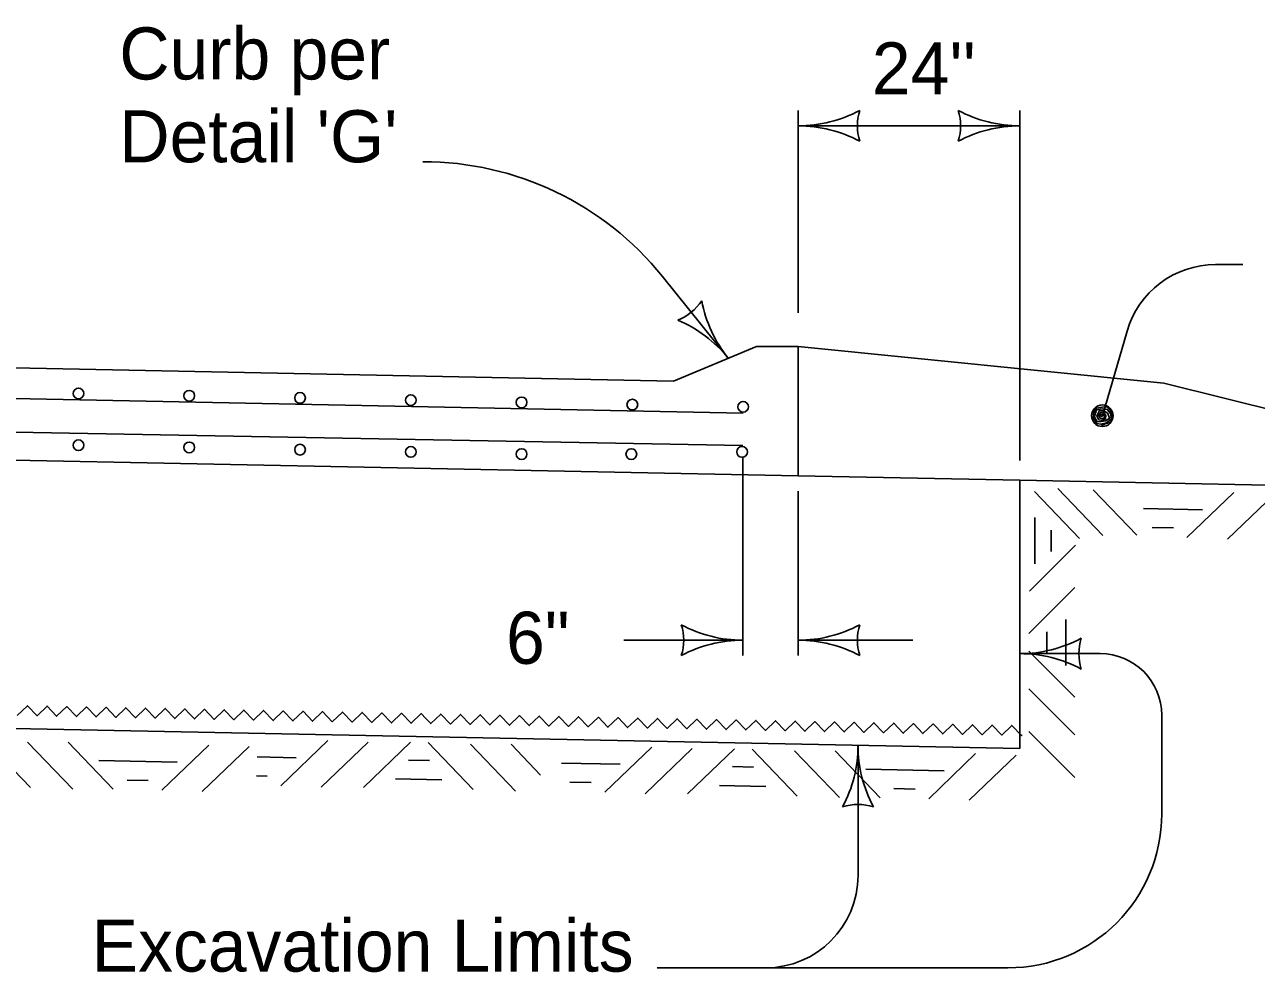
# Model space of a CAD drawing. Extents: x -2135039 to -2124495, y -2139046 to -2132546.
# Drawn here: x -2126978.8 to -2126600.4, y -2137518.2 to -2137227.1 of the extents above; entities that cross this region are included whole.
import ezdxf

# ---------------------------------------------------------------- set-up
doc = ezdxf.new("R2010")
doc.units = 0
doc.layers.add('BridgeSuperStructureExisting', color=7, linetype='Continuous')
doc.layers.add('dsnStdLabel', color=7, linetype='Continuous')

msp = doc.modelspace()

# ---------------------------------------------------------------- linework, layer by layer
at = {"layer": 'BridgeSuperStructureExisting'}
for p, q in [((-2126741.2, -2137315.6), (-2126741.2, -2137253.45)), ((-2126673.14, -2137360.94), (-2126673.14, -2137253.45)), ((-2126673.14, -2137258.17), (-2126741.2, -2137258.17)), ((-2126604.57, -2137300.82), (-2126612.95, -2137300.82)), ((-2126782.93, -2137304.43), (-2126762.67, -2137329.6)), ((-2126779.48, -2137336.57), (-2127489.73, -2137322.31)), ((-2127489.73, -2137322.31), (-2126779.48, -2137336.57)), ((-2126640.18, -2137321.24), (-2126647.76, -2137347.24)), ((-2126753.96, -2137325.99), (-2126779.48, -2137336.57)), ((-2126779.48, -2137336.57), (-2126753.96, -2137325.99)), ((-2126741.2, -2137325.99), (-2126753.96, -2137325.99)), ((-2126741.2, -2137325.99), (-2126753.96, -2137325.99)), ((-2126741.2, -2137365.7), (-2126741.2, -2137325.99)), ((-2126741.2, -2137365.7), (-2126741.2, -2137325.99)), ((-2126741.2, -2137325.99), (-2126628.92, -2137337.22)), ((-2127489.77, -2137331.8), (-2126758.11, -2137346.48)), ((-2126628.92, -2137337.22), (-2126380.66, -2137399.31)), ((-2126928.2, -2137342.96), (-2126928.2, -2137342.96)), ((-2126894.17, -2137343.64), (-2126894.17, -2137343.64)), ((-2126826.1, -2137345), (-2126826.1, -2137345)), ((-2127490.3, -2137350.67), (-2126741.2, -2137365.7)), ((-2127489.16, -2137350.69), (-2126741.2, -2137365.7)), ((-2126962.47, -2137354.64), (-2126962.47, -2137354.64)), ((-2126928.44, -2137355.33), (-2126928.44, -2137355.33)), ((-2126894.4, -2137356.01), (-2126894.4, -2137356.01)), ((-2126860.37, -2137356.69), (-2126860.37, -2137356.69)), ((-2126826.34, -2137357.38), (-2126826.34, -2137357.38)), ((-2126758.21, -2137360.18), (-2126758.21, -2137420.92)), ((-2126741.2, -2137365.7), (-2126673.14, -2137367.07)), ((-2126673.14, -2137449.49), (-2126673.14, -2137367.07)), ((-2126673.14, -2137367.07), (-2126495.29, -2137370.64)), ((-2126741.2, -2137370.43), (-2126741.2, -2137420.92)), ((-2126668.64, -2137370.55), (-2126654.79, -2137384.97)), ((-2126661.42, -2137369.62), (-2126647.57, -2137384.04)), ((-2126650.57, -2137369.95), (-2126637.18, -2137383.88)), ((-2126607.35, -2137370.82), (-2126621.77, -2137384.67)), ((-2126594.91, -2137371.29), (-2126609.33, -2137385.15)), ((-2126670.11, -2137401.17), (-2126655.96, -2137387.03)), ((-2126670.33, -2137414.18), (-2126656.19, -2137400.04)), ((-2126758.21, -2137416.2), (-2126794.75, -2137416.2)), ((-2126705.98, -2137416.2), (-2126741.2, -2137416.2)), ((-2126648.42, -2137420.32), (-2126673.14, -2137420.32)), ((-2126670.33, -2137419.59), (-2126656.19, -2137433.73)), ((-2126670.33, -2137431.17), (-2126656.19, -2137445.31)), ((-2127489.73, -2137433.1), (-2126673.14, -2137449.49)), ((-2126629.51, -2137439.23), (-2126629.51, -2137469.59)), ((-2126670.33, -2137444.23), (-2126656.19, -2137458.37)), ((-2126990.95, -2137447.02), (-2126977.09, -2137461.44)), ((-2126977.94, -2137447.51), (-2126964.09, -2137461.93)), ((-2126965.49, -2137447.53), (-2126951.64, -2137461.95)), ((-2126885.74, -2137447.04), (-2126900.16, -2137460.89)), ((-2126873.3, -2137447.52), (-2126887.72, -2137461.37)), ((-2126860.29, -2137447.55), (-2126874.71, -2137461.41)), ((-2126854.88, -2137447.66), (-2126841.02, -2137462.08)), ((-2126922.28, -2137448.4), (-2126936.7, -2137462.25)), ((-2126909.83, -2137448.87), (-2126924.26, -2137462.73)), ((-2126841.88, -2137448.15), (-2126828.02, -2137462.57)), ((-2126829.42, -2137448.17), (-2126820.32, -2137457.64)), ((-2126786.21, -2137449.04), (-2126800.63, -2137462.89)), ((-2126773.76, -2137449.51), (-2126788.19, -2137463.37)), ((-2126760.76, -2137449.55), (-2126775.18, -2137463.4)), ((-2126755.34, -2137449.66), (-2126741.49, -2137464.08)), ((-2126742.34, -2137450.14), (-2126728.49, -2137464.57)), ((-2126729.89, -2137450.17), (-2126716.04, -2137464.59)), ((-2126722.82, -2137448.49), (-2126722.82, -2137488.5)), ((-2126686.68, -2137451.03), (-2126701.1, -2137464.89)), ((-2126674.23, -2137451.51), (-2126688.66, -2137465.37)), ((-2126676.78, -2137516.85), (-2126784.55, -2137516.85))]:
    msp.add_line(p, q, dxfattribs=at)
for points in [[(-2126648.02, -2137350.28), (-2126646.9, -2137349.77), (-2126645.17, -2137349.24), (-2126644.83, -2137347.48), (-2126645.07, -2137345.93), (-2126646.18, -2137344.5), (-2126647.83, -2137344.64), (-2126649.57, -2137344.89), (-2126650.41, -2137346.27), (-2126650.56, -2137347.74), (-2126649.54, -2137349.65), (-2126648.26, -2137349.81), (-2126646.53, -2137349.37), (-2126645.1, -2137348.26), (-2126645.14, -2137346.61), (-2126646.26, -2137345.28), (-2126647.81, -2137345.13), (-2126649.56, -2137345.47), (-2126649.82, -2137346.45), (-2126650.17, -2137347.63), (-2126649.36, -2137349.07), (-2126648.09, -2137349.03), (-2126646.64, -2137348.79), (-2126645.59, -2137347.99), (-2126646.12, -2137346.54), (-2126647.21, -2137345.7), (-2126648.68, -2137345.64), (-2126649.04, -2137346.43), (-2126649.5, -2137347.32), (-2126648.79, -2137348.46), (-2126647.71, -2137348.72), (-2126646.75, -2137348.21), (-2126646.69, -2137347.14), (-2126647.19, -2137346.38), (-2126648.18, -2137346.11), (-2126648.65, -2137346.52), (-2126648.93, -2137347.11), (-2126648.42, -2137347.97), (-2126647.73, -2137348.14), (-2126647.06, -2137347.73), (-2126647.17, -2137347.16), (-2126647.67, -2137346.78), (-2126648.35, -2137346.8), (-2126648.34, -2137347.29), (-2126647.74, -2137347.56)], [(-2126635.1, -2137375.74), (-2126617.04, -2137376.1)], [(-2126668.53, -2137392.74), (-2126668.53, -2137378.54)], [(-2126663.44, -2137388.91), (-2126663.44, -2137382.37)], [(-2126632.45, -2137381.59), (-2126625.92, -2137381.72)], [(-2126658.98, -2137423.98), (-2126658.98, -2137409.79)], [(-2126664.83, -2137420.15), (-2126664.83, -2137413.62)], [(-2126981.1, -2137439.3), (-2126978.01, -2137436.33), (-2126975.05, -2137439.42), (-2126971.97, -2137436.45), (-2126969.01, -2137439.54), (-2126965.92, -2137436.58), (-2126962.96, -2137439.66), (-2126959.87, -2137436.7), (-2126956.9, -2137439.78), (-2126953.82, -2137436.82), (-2126950.85, -2137439.9), (-2126947.77, -2137436.94), (-2126944.81, -2137440.02), (-2126941.72, -2137437.06), (-2126938.76, -2137440.15), (-2126935.67, -2137437.18), (-2126932.71, -2137440.27), (-2126929.62, -2137437.3), (-2126928.15, -2137438.85)], [(-2126928.15, -2137438.85), (-2126926.66, -2137440.39), (-2126923.57, -2137437.42), (-2126920.61, -2137440.51), (-2126917.53, -2137437.55), (-2126914.57, -2137440.63), (-2126911.48, -2137437.67), (-2126908.51, -2137440.75), (-2126905.43, -2137437.79), (-2126902.46, -2137440.87), (-2126899.38, -2137437.91), (-2126896.42, -2137441), (-2126893.33, -2137438.03), (-2126890.37, -2137441.12), (-2126887.29, -2137438.15), (-2126884.32, -2137441.24), (-2126881.23, -2137438.27), (-2126878.27, -2137441.36), (-2126875.18, -2137438.4), (-2126872.22, -2137441.48), (-2126869.14, -2137438.52), (-2126866.18, -2137441.6), (-2126863.09, -2137438.64), (-2126860.13, -2137441.72), (-2126857.04, -2137438.76), (-2126855.56, -2137440.3)], [(-2126855.56, -2137440.3), (-2126854.08, -2137441.84), (-2126850.99, -2137438.88), (-2126848.03, -2137441.97), (-2126844.94, -2137439), (-2126841.98, -2137442.09), (-2126838.9, -2137439.12), (-2126835.93, -2137442.21), (-2126832.85, -2137439.24), (-2126829.88, -2137442.33), (-2126826.79, -2137439.37), (-2126823.83, -2137442.45), (-2126820.75, -2137439.49), (-2126817.79, -2137442.58), (-2126814.7, -2137439.61), (-2126811.74, -2137442.69), (-2126808.65, -2137439.73), (-2126805.69, -2137442.81), (-2126802.6, -2137439.85), (-2126799.64, -2137442.94), (-2126796.55, -2137439.98), (-2126793.59, -2137443.06), (-2126790.51, -2137440.1), (-2126787.54, -2137443.18), (-2126784.46, -2137440.21), (-2126782.97, -2137441.76)], [(-2126782.97, -2137441.76), (-2126781.49, -2137443.3), (-2126778.4, -2137440.34), (-2126775.44, -2137443.42), (-2126772.36, -2137440.46), (-2126769.4, -2137443.55), (-2126766.31, -2137440.58), (-2126763.35, -2137443.67), (-2126760.26, -2137440.7), (-2126757.3, -2137443.78), (-2126754.21, -2137440.82), (-2126751.25, -2137443.91), (-2126748.16, -2137440.95), (-2126745.2, -2137444.03), (-2126742.12, -2137441.07), (-2126739.15, -2137444.15), (-2126736.07, -2137441.19), (-2126733.1, -2137444.27), (-2126730.02, -2137441.31), (-2126727.05, -2137444.39), (-2126723.97, -2137441.43), (-2126721, -2137444.52), (-2126717.92, -2137441.55), (-2126714.96, -2137444.64), (-2126711.87, -2137441.67), (-2126710.39, -2137443.22)], [(-2126710.39, -2137443.22), (-2126708.91, -2137444.76), (-2126705.82, -2137441.79), (-2126702.86, -2137444.88), (-2126699.77, -2137441.92), (-2126696.81, -2137445), (-2126693.72, -2137442.04), (-2126690.76, -2137445.12), (-2126687.68, -2137442.16), (-2126684.71, -2137445.24), (-2126681.63, -2137442.28), (-2126678.66, -2137445.37), (-2126675.58, -2137442.4), (-2126672.61, -2137445.49), (-2126672.4, -2137445.3)], [(-2126956.02, -2137453.2), (-2126931.97, -2137453.68)], [(-2126907.46, -2137452.08), (-2126895.43, -2137452.32)], [(-2126860.96, -2137453.04), (-2126854.43, -2137453.17)], [(-2126813.96, -2137453.96), (-2126795.9, -2137454.32)], [(-2126761.42, -2137455.03), (-2126754.89, -2137455.16)], [(-2126947.38, -2137459.17), (-2126940.85, -2137459.3)], [(-2126907.58, -2137457.88), (-2126904.31, -2137457.94)], [(-2126864.9, -2137458.81), (-2126850.72, -2137459.1)], [(-2126720.42, -2137455.83), (-2126696.37, -2137456.32)], [(-2126811.31, -2137459.81), (-2126804.78, -2137459.94)], [(-2126765.37, -2137460.81), (-2126751.18, -2137461.1)], [(-2126711.78, -2137461.81), (-2126705.24, -2137461.94)]]:
    msp.add_lwpolyline(points, dxfattribs=at)
for centre, radius in [((-2126962.31, -2137340.41), 1.65), ((-2126928.28, -2137341.09), 1.65), ((-2126894.24, -2137341.77), 1.65), ((-2126860.21, -2137342.46), 1.65), ((-2126826.18, -2137343.14), 1.65), ((-2126792.15, -2137343.82), 1.65), ((-2126758.11, -2137344.5), 1.65), ((-2126647.76, -2137347.24), 3.31), ((-2126962.31, -2137356.29), 1.65), ((-2126928.28, -2137356.97), 1.65), ((-2126894.24, -2137357.66), 1.65), ((-2126860.21, -2137358.34), 1.65), ((-2126758.44, -2137358.34), 1.65), ((-2126826.18, -2137359.03), 1.65), ((-2126792.47, -2137359.03), 1.65)]:
    msp.add_circle(centre, radius, dxfattribs=at)
for centre, radius, start, end in [((-2126741.2, -2137218), 40.18, 270, 298.0725), ((-2126741.2, -2137218), 40.18, 270, 298.0725), ((-2126707.51, -2137258.17), 15.52, 162.2666, 197.7334), ((-2126707.51, -2137258.17), 15.52, 162.2666, 197.7334), ((-2126706.82, -2137258.17), 15.52, 342.2666, 17.7334), ((-2126673.14, -2137218), 40.18, 241.9275, 270), ((-2126706.82, -2137258.17), 15.52, 342.2666, 17.7334), ((-2126673.14, -2137218), 40.18, 241.9275, 270), ((-2126741.2, -2137298.35), 40.18, 61.9275, 90), ((-2126741.2, -2137298.35), 40.18, 61.9275, 90), ((-2126673.14, -2137298.35), 40.18, 90, 118.0725), ((-2126673.14, -2137298.35), 40.18, 90, 118.0725), ((-2126856.56, -2137363.71), 94.53, 38.8378, 90), ((-2126612.95, -2137329.18), 28.36, 90, 163.739), ((-2126783.79, -2137303.36), 15.52, 291.1048, 326.5715), ((-2126731.37, -2137304.41), 40.18, 190.7656, 218.8381), ((-2126793.96, -2137354.8), 40.18, 38.8381, 66.9106), ((-2126791.9, -2137416.2), 15.52, 342.2666, 17.7334), ((-2126758.21, -2137376.02), 40.18, 241.9275, 270), ((-2126741.2, -2137376.02), 40.18, 270, 298.0725), ((-2126707.51, -2137416.2), 15.52, 162.2666, 197.7334), ((-2126758.21, -2137456.37), 40.18, 90, 118.0725), ((-2126741.2, -2137456.37), 40.18, 61.9275, 90), ((-2126673.14, -2137380.15), 40.18, 270, 298.0725), ((-2126639.45, -2137420.32), 15.52, 162.2666, 197.7334), ((-2126673.14, -2137460.5), 40.18, 61.9275, 90), ((-2126648.42, -2137439.23), 18.91, 0, 90), ((-2126763, -2137448.49), 40.18, 331.9275, 360), ((-2126682.65, -2137448.49), 40.18, 180, 208.0725), ((-2126722.82, -2137482.18), 15.52, 72.2666, 107.7334), ((-2126676.78, -2137469.59), 47.27, 270, 360), ((-2126751.18, -2137488.5), 28.36, 270, 360)]:
    msp.add_arc(centre, radius, start, end, dxfattribs=at)
at = {"layer": 'dsnStdLabel'}
msp.add_line((-2126758.22, -2137356.41), (-2127489.77, -2137342.86), dxfattribs=at)

# ---------------------------------------------------------------- texts
for s, p in [('Curb per ', (-2126949.77, -2137243.93)), ("24''", (-2126718.56, -2137248.53)), ("Detail 'G'", (-2126949.77, -2137269.38)), ('6"', (-2126830.94, -2137423.45)), ('Excavation Limits', (-2126958.25, -2137518.02))]:
    msp.add_text(s, height=16, dxfattribs=at).set_placement(p)

doc.saveas('drawing.dxf')
